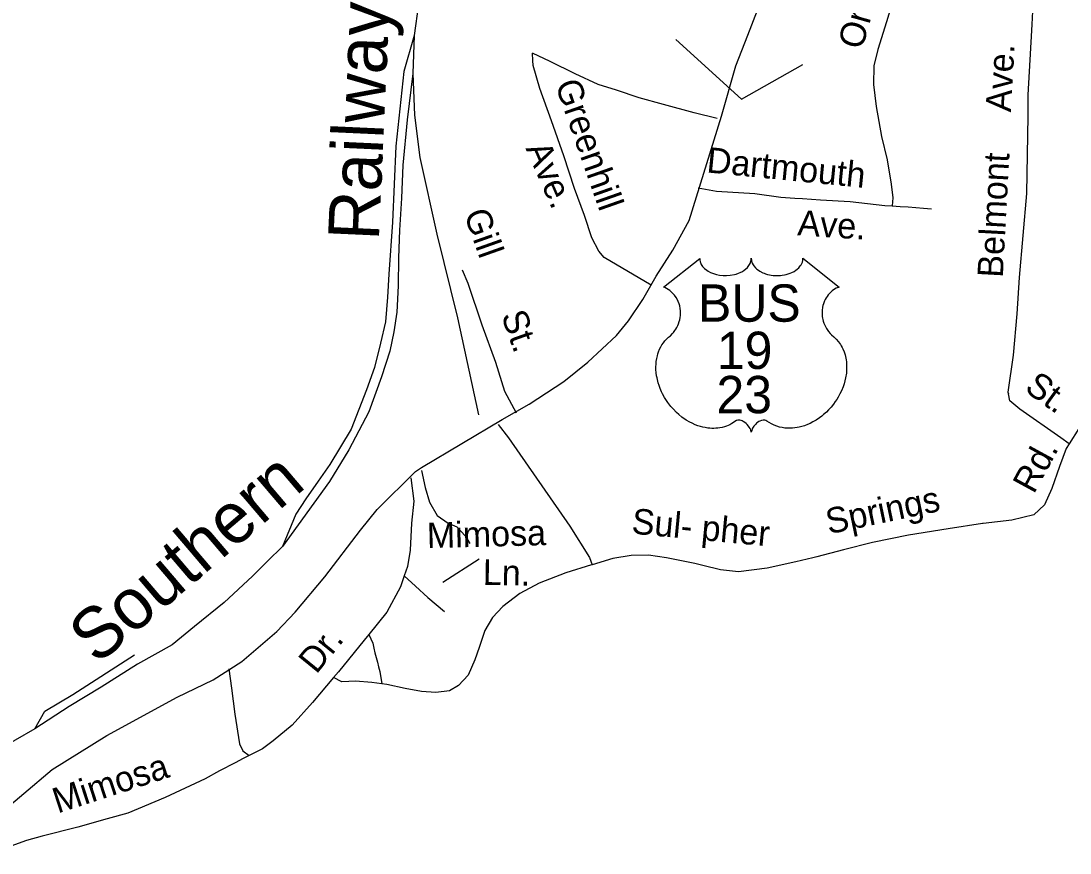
# Model space of a CAD drawing. Extents: x 925297 to 940193, y 663541 to 689899.
# Drawn here: x 927164 to 927782, y 687866 to 688356 of the extents above; entities that cross this region are included whole.
import ezdxf

# ---------------------------------------------------------------- set-up
doc = ezdxf.new("R2010")
doc.units = 0
doc.layers.add('Default', color=7, linetype='Continuous')

msp = doc.modelspace()

# ---------------------------------------------------------------- linework, layer by layer
at = {"layer": 'Default'}
msp.add_line((927395.33, 688347.45), (927394.49, 688325.15), dxfattribs=at)
for points in [[(927535.31, 688724.53), (927528.13, 688713.13), (927514.88, 688693.7), (927503.08, 688674.77), (927492.49, 688657.39), (927485.11, 688642.58), (927472.28, 688621.57), (927462.12, 688602.35), (927450.74, 688578.16), (927442.35, 688555.48), (927435.71, 688538.55), (927426.53, 688515.9), (927418.32, 688486.39), (927405.54, 688421.54), (927395.33, 688347.45)], [(927712.46, 688479.88), (927709.71, 688473.43), (927706.07, 688459.81), (927700.87, 688443.87), (927694.3, 688423.48), (927689.68, 688407.88), (927684.02, 688390.05), (927678.89, 688373.19), (927673.64, 688355.41), (927668.57, 688339.18), (927666.26, 688329.54), (927665.91, 688318.63), (927667.61, 688305.53), (927670.65, 688287.95), (927673.95, 688274.17), (927676.34, 688259.83), (927677.3, 688251.84), (927676.93, 688246.95)], [(927780.59, 688438.49), (927776.24, 688434.35), (927767.51, 688424.42), (927764.03, 688419.9), (927762.91, 688414.82), (927761.61, 688395.79), (927760.33, 688373.72), (927759.24, 688353.91), (927758.04, 688333.09), (927756.95, 688312.44), (927756.87, 688300.05), (927756.12, 688254.29), (927751.73, 688204.8), (927750.41, 688183.29), (927748.19, 688158.95), (927745.23, 688137.21), (927745.44, 688136.29)], [(927148.43, 687886.48), (927182.07, 687914.78), (927214.26, 687934.85), (927255.76, 687957.45), (927276.97, 687967.71), (927293.78, 687978.46), (927314.32, 687996.21), (927325.26, 688007.61), (927342.73, 688028.37), (927363.68, 688055.86), (927373.46, 688067.98), (927396.08, 688090.38), (927399.59, 688092.72), (927447.25, 688121.16), (927463.05, 688130.05), (927483.59, 688143.59), (927497.6, 688154.81), (927514.59, 688170.59), (927521.6, 688179.24), (927530, 688191.85), (927537.94, 688205.59), (927547.69, 688220.82), (927557.27, 688238.48), (927576.51, 688299.86), (927584.78, 688329.55), (927591.84, 688347.72), (927607.69, 688388.45)], [(927395.33, 688347.45), (927389.33, 688326.31), (927384.51, 688282.3), (927382.56, 688237.44), (927380.31, 688206.77), (927379.71, 688193.13), (927378.5, 688178.72), (927375.56, 688166.18), (927371.93, 688151.81), (927367.33, 688138.51), (927358.14, 688115.33), (927345.71, 688094.58), (927338.76, 688084.74), (927331.53, 688074.38), (927325.57, 688065.31), (927317.71, 688046.31)], [(927549.54, 688345.05), (927588.14, 688309.85), (927624.29, 688330.38)], [(927573.94, 688298.51), (927560.37, 688301.81), (927542.2, 688306.8), (927528, 688310.77), (927514.49, 688315.16), (927503.8, 688318.58), (927490.28, 688324.79), (927475.4, 688332.22), (927465.1, 688337.02)], [(927534.89, 688200.27), (927507.3, 688216.54), (927504.06, 688220.24), (927500.08, 688228.13), (927495.74, 688241.35), (927489.75, 688257.31), (927483.44, 688276.47), (927476.29, 688297.1), (927469.31, 688316.25), (927465.36, 688329.76), (927465.16, 688332.75), (927465.1, 688337.02)], [(927394.49, 688325.15), (927391.12, 688297.65), (927388.55, 688270.93), (927387.9, 688251.51), (927386.73, 688232.64), (927386.08, 688216.37), (927385.95, 688199.83), (927385.11, 688184.36), (927383.31, 688172.85), (927380.91, 688161.34), (927376.15, 688146.21), (927368.52, 688125.62), (927356.91, 688103.28), (927345.51, 688084.6), (927317.71, 688046.31)], [(927394.49, 688325.15), (927395.51, 688300.45), (927398.75, 688275.45), (927408.74, 688230.36), (927420.95, 688181.02), (927433.32, 688123.8)], [(927562.69, 688257.75), (927573.43, 688255.65), (927596.03, 688254.29), (927611.3, 688252.11), (927619.57, 688251.6)], [(927619.57, 688251.6), (927624.05, 688251.32), (927634.66, 688250.58), (927652.29, 688249.68), (927672.69, 688247.28), (927676.93, 688246.95)], [(927676.93, 688246.95), (927681.75, 688246.57), (927686.34, 688246.42), (927690.93, 688246.15), (927695.5, 688245.76), (927700.07, 688245.24)], [(927455.64, 688124.8), (927448.78, 688137.68), (927443.37, 688154.65), (927435.42, 688176.68), (927427.11, 688201.23), (927423.86, 688209.18)], [(927781.26, 688106.84), (927776.29, 688110.3), (927752.23, 688127.11), (927746.41, 688132.01), (927745.44, 688136.29)], [(927801.78, 688130.23), (927800.01, 688128.42), (927797.64, 688126.61), (927787.02, 688115.78), (927781.26, 688106.84)], [(927444.73, 688118.22), (927451, 688110.27), (927487.04, 688058.14), (927498.65, 688039.8), (927500.13, 688035.52)], [(927781.26, 688106.84), (927779.46, 688104.04), (927775.49, 688093.31), (927770.97, 688080.5), (927766.83, 688070.82), (927760.51, 688064.99), (927747.56, 688061.76), (927730.58, 688059.86), (927730.29, 688059.82)], [(927399.68, 688091.09), (927401.83, 688080.97), (927404.27, 688072.32), (927408.86, 688064.49), (927415.35, 688059.89), (927420.49, 688057.73), (927425.35, 688052.59), (927428.06, 688048)], [(927393.3, 688086.63), (927395.08, 688073.04), (927393.83, 688059.92), (927392.98, 688044.14), (927391.32, 688034.47), (927389.49, 688028.86)], [(927730.29, 688059.82), (927710.03, 688056.69), (927686.53, 688052.95), (927665.46, 688048.64), (927648.29, 688044.32), (927632.58, 688040.1), (927630.21, 688039.57)], [(927317.71, 688046.31), (927308.93, 688037.56), (927300.1, 688028.81), (927283.31, 688013.13), (927265.9, 687999.04), (927252.75, 687988.27), (927232.31, 687976.87), (927210.91, 687963.38), (927192.1, 687951.94), (927171.75, 687938.7)], [(927433.65, 688038.85), (927412.16, 688024.94)], [(927500.13, 688035.52), (927499.83, 688035.43), (927484.7, 688030.7), (927468.92, 688024.64), (927457.55, 688018.52), (927447.56, 688010.81), (927441.5, 688004.29), (927436.96, 687996.67), (927433.53, 687986.65), (927431.09, 687979.4), (927427.15, 687970.43)], [(927565.47, 688034.97), (927560.63, 688036.17), (927544.07, 688039.49), (927533.45, 688041.21), (927523.19, 688040.96), (927512.42, 688039.23), (927500.13, 688035.52)], [(927630.21, 688039.57), (927620.13, 688037.28), (927603.26, 688033.53), (927586.34, 688031.35), (927575.75, 688032.42), (927565.47, 688034.97)], [(927389.49, 688028.86), (927387.37, 688022.37), (927379.26, 688007.61), (927368.61, 687994.33)], [(927389.49, 688028.86), (927396.02, 688022.91), (927403.36, 688016.09), (927413.14, 688007.89)], [(927368.61, 687994.33), (927365.93, 687990.99), (927350.71, 687972.36), (927347.84, 687968.94)], [(927368.61, 687994.33), (927370.93, 687989.21), (927371.56, 687986.39), (927372.21, 687983.62), (927372.9, 687980.85), (927373.63, 687978.09), (927374.39, 687975.33), (927375.18, 687972.57), (927376.26, 687965.28)], [(927171.75, 687938.7), (927177.74, 687949.08), (927194.15, 687958.99), (927230.52, 687982.42)], [(927286.03, 687974.04), (927287.63, 687962.66), (927289.65, 687947.49), (927292.39, 687930), (927294.29, 687925.87), (927298.02, 687922.97)], [(927347.84, 687968.94), (927335.44, 687954.19), (927323.51, 687940.96), (927312.3, 687931.59), (927305.86, 687926.99), (927298.02, 687922.97)], [(927376.26, 687965.28), (927370.41, 687966.02), (927360.73, 687966.87), (927356.92, 687966.62), (927352.74, 687966.48), (927347.84, 687968.94)], [(927427.15, 687970.43), (927427.09, 687970.31), (927421.45, 687964.25), (927416.17, 687961.22), (927408.07, 687960.24), (927399.61, 687960.85), (927390.04, 687962.46), (927379.2, 687964.9), (927376.26, 687965.28)], [(927171.75, 687938.7), (927148.43, 687925.34)], [(927289.86, 687918.78), (927280.7, 687914.08), (927272.09, 687909.34), (927248.56, 687898.3), (927226.69, 687889.1), (927214.43, 687885.67), (927197.14, 687880.76), (927176.21, 687875.52), (927166.86, 687872.95), (927155.48, 687868.9), (927151.04, 687866.79), (927148.43, 687865.55)], [(927298.02, 687922.97), (927294.58, 687921.21), (927289.86, 687918.78)]]:
    msp.add_lwpolyline(points, dxfattribs=at)
msp.add_lwpolyline([(927563.57, 688216.06), (927563.62, 688215.18), (927563.83, 688214.13), (927564, 688213.59), (927564.49, 688212.56), (927565.29, 688211.35), (927566.41, 688210.15), (927567.68, 688209.11), (927568.54, 688208.56), (927569.99, 688207.78), (927571.63, 688207.09), (927573.46, 688206.56), (927575.33, 688206.18), (927577.38, 688205.96), (927579.4, 688205.92), (927581.59, 688206.08), (927584, 688206.55), (927585.11, 688206.84), (927586.36, 688207.26), (927587.51, 688207.74), (927588.78, 688208.42), (927589.8, 688209.07), (927590.59, 688209.65), (927591.72, 688210.73), (927592.62, 688211.85), (927593, 688212.48), (927593.32, 688213.08), (927593.77, 688214.36), (927593.89, 688214.93), (927593.98, 688216.1), (927594.06, 688215.11), (927594.16, 688214.5), (927594.32, 688213.9), (927594.57, 688213.26), (927595.02, 688212.35), (927595.53, 688211.6), (927596.47, 688210.48), (927597.06, 688209.93), (927597.6, 688209.49), (927599.05, 688208.5), (927600.74, 688207.64), (927601.56, 688207.28), (927602.42, 688206.98), (927603.5, 688206.65), (927604.61, 688206.39), (927605.72, 688206.2), (927606.85, 688206.03), (927608, 688205.95), (927608.95, 688205.92), (927610.1, 688205.93), (927611.17, 688206), (927612.26, 688206.12), (927613.47, 688206.32), (927614.43, 688206.54), (927615.71, 688206.87), (927616.87, 688207.29), (927617.88, 688207.73), (927619.2, 688208.42), (927620.27, 688209.09), (927621.05, 688209.71), (927621.98, 688210.57), (927622.86, 688211.59), (927623.37, 688212.33), (927623.73, 688213.09), (927624.07, 688213.9), (927624.28, 688214.75), (927624.38, 688215.49), (927624.4, 688216.12), (927645.66, 688199.19), (927645.16, 688199), (927644, 688198.43), (927643.08, 688197.89), (927641.62, 688196.86), (927640.99, 688196.3), (927640.37, 688195.71), (927639.79, 688195.08), (927639.28, 688194.49), (927638.67, 688193.64), (927638.11, 688192.78), (927637.57, 688191.84), (927637.18, 688191.02), (927636.53, 688189.32), (927636.21, 688188.24), (927636.01, 688187.32), (927635.76, 688185.42), (927635.7, 688184.52), (927635.7, 688183.63), (927635.75, 688182.68), (927635.83, 688181.78), (927636, 688180.84), (927636.15, 688180.01), (927636.41, 688178.99), (927636.79, 688177.81), (927637.25, 688176.67), (927638.23, 688174.82), (927639.47, 688172.94), (927640.37, 688171.88), (927641.24, 688170.98), (927642.56, 688169.87), (927643.27, 688169.25), (927644.08, 688168.43), (927645.41, 688166.88), (927645.95, 688166.16), (927646.5, 688165.34), (927647, 688164.5), (927647.5, 688163.59), (927647.9, 688162.8), (927648.65, 688160.98), (927649.2, 688159.21), (927649.45, 688158.28), (927649.84, 688156.2), (927649.99, 688155.17), (927650.16, 688153.13), (927650.16, 688150.67), (927649.98, 688148.33), (927649.54, 688145.61), (927649.17, 688143.98), (927648.61, 688142.08), (927648.07, 688140.43), (927647.1, 688138.01), (927646.24, 688136.25), (927645.12, 688134.19), (927644.36, 688132.95), (927643.47, 688131.62), (927642.35, 688130.08), (927641.04, 688128.45), (927639.47, 688126.73), (927638.21, 688125.46), (927636.55, 688123.98), (927635.55, 688123.15), (927634.11, 688122.07), (927632.16, 688120.76), (927630.22, 688119.65), (927628.58, 688118.81), (927627.12, 688118.18), (927625.24, 688117.46), (927622.1, 688116.59), (927620.96, 688116.36), (927619.6, 688116.16), (927618.34, 688116.03), (927617.11, 688115.95), (927615.45, 688115.95), (927613.8, 688116.08), (927612.25, 688116.31), (927610.63, 688116.64), (927608.93, 688117.15), (927607.4, 688117.75), (927605.84, 688118.52), (927603.21, 688120.17), (927602.45, 688120.58), (927602.02, 688120.69), (927601.01, 688120.74), (927600.05, 688120.54), (927599.07, 688120.15), (927598.48, 688119.83), (927597.7, 688119.32), (927597.1, 688118.84), (927596.37, 688118.15), (927595.86, 688117.57), (927595.48, 688117.12), (927594.74, 688115.95), (927594.48, 688115.4), (927594.2, 688114.69), (927593.96, 688113.63), (927593.62, 688114.96), (927593.24, 688115.84), (927592.78, 688116.59), (927592.31, 688117.26), (927591.57, 688118.11), (927590.91, 688118.75), (927590.1, 688119.41), (927589.25, 688119.92), (927588.57, 688120.27), (927587.94, 688120.51), (927587.17, 688120.7), (927586.54, 688120.75), (927586.03, 688120.74), (927585.32, 688120.58), (927584.36, 688119.89), (927583.45, 688119.26), (927582.46, 688118.64), (927581.28, 688118.01), (927580.41, 688117.61), (927579.38, 688117.21), (927578.18, 688116.81), (927576.87, 688116.47), (927575.53, 688116.21), (927574.35, 688116.02), (927573.08, 688115.9), (927571.94, 688115.87), (927570.75, 688115.88), (927569.63, 688115.97), (927568.34, 688116.08), (927566.73, 688116.32), (927565.4, 688116.62), (927563.99, 688117), (927562.55, 688117.45), (927561, 688118.04), (927559.07, 688118.88), (927557.73, 688119.57), (927555.61, 688120.79), (927553.12, 688122.51), (927551.24, 688124.03), (927549.87, 688125.27), (927547.85, 688127.33), (927546.66, 688128.68), (927544.8, 688131.09), (927543.61, 688132.83), (927542.83, 688134.12), (927541.7, 688136.18), (927541.08, 688137.47), (927540.28, 688139.35), (927539.65, 688141.07), (927539.12, 688142.71), (927538.84, 688143.75), (927538.43, 688145.57), (927538.19, 688146.86), (927537.95, 688148.63), (927537.82, 688150.51), (927537.79, 688152.23), (927537.84, 688153.66), (927538, 688155.33), (927538.28, 688157.1), (927538.62, 688158.62), (927538.93, 688159.71), (927539.38, 688161.04), (927539.98, 688162.51), (927540.68, 688163.92), (927541.35, 688165.09), (927542.19, 688166.34), (927543.02, 688167.41), (927544.11, 688168.59), (927545.24, 688169.67), (927546.27, 688170.51), (927547.5, 688171.72), (927548.15, 688172.45), (927548.92, 688173.47), (927549.53, 688174.41), (927550.02, 688175.25), (927550.67, 688176.49), (927551.06, 688177.42), (927551.55, 688178.85), (927551.79, 688179.86), (927552.04, 688181.15), (927552.21, 688182.37), (927552.27, 688183.89), (927552.23, 688185.15), (927552.07, 688186.62), (927551.79, 688188.02), (927551.46, 688189.25), (927550.93, 688190.66), (927550.45, 688191.69), (927549.63, 688193.08), (927548.73, 688194.38), (927547.79, 688195.43), (927546.85, 688196.37), (927545.95, 688197.08), (927545.09, 688197.69), (927544.01, 688198.35), (927542.97, 688198.86), (927542.31, 688199.12)], close=True, dxfattribs=at)

# ---------------------------------------------------------------- texts
for s, height, rotation, p in [('Ormond', 15, 74.36337, (927659.24, 688338.59)), ('Railway', 30, 87.41408, (927374.48, 688226.23)), ('Ave.', 15, 86.90742, (927746.98, 688302.06)), ('Greenhill', 15, 289.35063, (927478.21, 688318.72)), ('Ave.', 15, 293.56194, (927460.86, 688280.9)), ('Dartmouth', 15, 354.36219, (927567.28, 688266.79)), ('Belmont', 15, 86.90742, (927742.15, 688204.45)), ('Gill', 15, 289.52739, (927424.49, 688242.39)), ('Ave.', 15, 356.30492, (927620.88, 688229.69)), ('St.', 15, 289.52739, (927446.46, 688182.49)), ('St.', 15, 324.11997, (927754.32, 688138.28)), ('Rd.', 15, 61.438, (927760.46, 688076.69)), ('Southern', 30, 40.40771, (927208.4, 687975.96)), ('Springs', 15, 11.81035, (927639.56, 688053.41)), ('Sul- pher', 15, 354.63394, (927523.08, 688053.9)), ('Mimosa', 15, 1.4793, (927402.97, 688045.24)), ('Ln.', 15, 359.04613, (927435.69, 688023.64)), ('Dr.', 15, 50.86993, (927337.65, 687970.54)), ('Mimosa', 15, 18.0278, (927185.22, 687888.76))]:
    msp.add_text(s, height=height, rotation=rotation, dxfattribs=at).set_placement(p)
for s, p in [('BUS', (927562.59, 688178.74)), ('19', (927573.68, 688150.88)), ('23', (927573.46, 688124.79))]:
    msp.add_text(s, height=22, dxfattribs=at).set_placement(p)

doc.saveas('drawing.dxf')
